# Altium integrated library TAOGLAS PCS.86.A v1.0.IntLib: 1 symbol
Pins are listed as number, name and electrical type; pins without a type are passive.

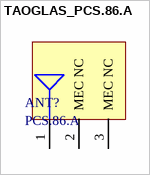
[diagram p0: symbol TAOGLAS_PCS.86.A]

## TAOGLAS_PCS.86.A
designator ANT?, comment PCS.86.A
Reach - Low Profile Wideband Cellular - 5G/4G SMD Antenna; ComponentLibStatus: Created; MFG: Taoglas
footprint TAOGLAS_PCS.86.A (Reach - Low Profile Wideband Cellular - 5G/4G SMD Antenna)
pins: 1 RF FEED, 2 MEC NC, 3 MEC NC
